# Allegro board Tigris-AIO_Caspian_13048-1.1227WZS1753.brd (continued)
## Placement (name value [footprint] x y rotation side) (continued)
C672  SCD1U16V2KX-3GP  [C402H22]  61.09 50.53 270 bottom
C673  SC10U16V6KX-2GP  [C1206H71]  129.32 49.77 270 bottom
C674  SCD1U16V2KX-3GP  [C402H22]  61.09 48.37 270 bottom
C675  SCD01U16V2KX-3GP  [C402H22]  57.1 48.78 0 bottom
C676  SCD1U16V2KX-3GP  [C402H22]  61.09 49.26 270 bottom
C677  SCD1U16V2KX-3GP  [C402H22]  61.09 46.97 270 bottom
C678  SCD1U16V2KX-3GP  [C402H22]  44.3 44.79 0 bottom
C679  SC3D3U10V5KX-2GP  [C805H38]  53.62 44.66 180 bottom
C680  SC10U25V5KX-GP  [C805H56]  45.75 43.9 180 bottom
C681  SCD01U16V2KX-3GP  [C402H22]  49.94 41.36 0 bottom
C682  SC10U25V5KX-GP  [C805H56]  161.67 36.05 90 bottom
C683  SCD1U16V2KX-3GP  [C402H22]  48.76 39.89 90 bottom
C684  SCD1U25V3KX-GP  [C603H36]  157.61 35.67 270 bottom
C685  SCD1U16V2KX-3GP  [C402H22]  61.85 38.08 180 bottom
C686  SCD1U16V2KX-3GP  [C402H22]  29.84 38.21 180 bottom
C687  SCD1U16V2KX-3GP  [C402H22]  27.94 38.08 180 bottom
C688  SCD1U16V2KX-3GP  [C402H22]  33.66 37.83 0 bottom
C689  SCD1U25V3KX-GP  [C603H36]  161.8 33.38 90 bottom
C690  SC10U25V5KX-GP  [C805H56]  157.42 33.16 270 bottom
C691  SCD1U16V2KX-3GP  [C402H22]  56.79 36.53 180 bottom
C692  SCD1U16V2KX-3GP  [C402H22]  18.16 36.56 0 bottom
C693  SCD1U16V2KX-3GP  [C402H22]  17.3 36.56 0 bottom
C694  SCD1U16V2KX-3GP  [C402H22]  12.85 36.56 180 bottom
C695  SCD1U16V2KX-3GP  [C402H22]  48.72 36.41 180 bottom
C696  SCD1U16V2KX-3GP  [C402H22]  59.27 35.91 90 bottom
C697  SC1U10V2KX-1GP  [C402H22]  26.67 35.8 270 bottom
C698  SCD1U16V2KX-3GP  [C402H22]  29.46 34.3 0 bottom
C699  SCD1U16V2KX-3GP  [C402H22]  33.66 34.4 180 bottom
C700  SCD1U16V2KX-3GP  [C402H22]  30.48 34.4 0 bottom
C701  SCD1U16V2KX-3GP  [C402H22]  28.07 34.43 0 bottom
C702  SC2D2U10V3KX-1GP  [C603H36]  36.83 34.02 90 bottom
C703  SCD1U16V2KX-3GP  [C402H22]  23.24 33.87 90 bottom
C704  SCD1U16V2KX-3GP  [C402H22]  131.5 32.7 0 bottom
C705  SCD1U16V2KX-3GP  [C402H22]  41.5 32.57 270 bottom
C706  SCD1U16V2KX-3GP  [C402H22]  44.53 32.65 90 bottom
C707  SC10U10V5KX-2GP  [C805H54]  132.97 32.34 0 bottom
C708  SC10P50V2JN-4GP  [C402H22]  10.01 25.46 0 top
C709  SCD1U16V2KX-3GP  [C402H22]  25.53 26.27 180 bottom
C710  SCD1U16V2KX-3GP  [C402H22]  25.96 30.84 90 bottom
C711  SC10P50V2JN-4GP  [C402H22]  10.01 27.37 180 top
C712  SCD1U16V2KX-3GP  [C402H22]  27.05 26.27 180 bottom
C713  SCD1U16V2KX-3GP  [C402H22]  64.14 28.43 0 bottom
C714  SCD1U10V2KX-4GP  [C402H20]  55.24 27.29 0 bottom
C715  SC10U10V5KX-2GP  [C805H54]  128.83 26.55 270 bottom
C716  SC1U10V2KX-1GP  [C402H22]  23.5 25.76 180 bottom
C717  SCD1U16V2KX-3GP  [C402H22]  22.1 25.64 180 bottom
C718  SC1U10V2KX-1GP  [C402H22]  19.05 25.59 0 bottom
C719  SCD1U16V2KX-3GP  [C402H22]  18.16 25.57 180 bottom
C720  SCD1U16V2KX-3GP  [C402H22]  129.13 24.01 270 bottom
C721  SCD1U10V2KX-4GP  [C402H20]  52.96 23.1 180 bottom
C722  SC100P50V2JN-3GP  [C402H22]  31.62 21.98 0 bottom
C723  SC100P50V2JN-3GP  [C402H22]  33.75 21.98 0 bottom
C724  SCD1U16V2KX-3GP  [C402H22]  63.75 21.19 180 bottom
C725  SCD1U16V2KX-3GP  [C402H22]  62.87 21.19 180 bottom
C726  SCD1U16V2KX-3GP  [C402H22]  34.85 15.96 180 bottom
C727  SC100P50V2JN-3GP  [C402H22]  33.43 15.43 270 bottom
C728  SC100P50V2JN-3GP  [C402H22]  33.93 14 180 bottom
C729  SC10U6D3V3MX-GP  [C603H38]  172.36 83.17 90 bottom
C732  SCD1U16V2KX-3GP  [C402H22]  25.6 141.74 180 top
C733  SCD1U25V3KX-GP  [C603H36]  28.7 147.68 180 top
C734  SCD47U25V3KX-1GP  [C603H36]  31.88 161.02 270 top
C735  SC1U25V3KX-1-GP  [C603H36]  26.04 154.54 90 top
C736  SCD22U10V2KX-1GP  [C402H22]  92.08 104.76 0 bottom
C737  SCD22U10V2KX-1GP  [C402H22]  81.15 106.38 0 bottom
C738  SCD22U10V2KX-1GP  [C402H22]  86.11 105.14 0 bottom
C739  SCD22U10V2KX-1GP  [C402H22]  84.2 106.41 0 bottom
C740  SCD22U10V2KX-1GP  [C402H22]  92.96 104.76 0 bottom
C741  SCD22U10V2KX-1GP  [C402H22]  90.3 103.62 0 bottom
C742  SCD22U10V2KX-1GP  [C402H22]  79.86 104.15 0 bottom
C743  SCD22U10V2KX-1GP  [C402H22]  88.27 107.3 0 bottom
C744  SCD22U10V2KX-1GP  [C402H22]  82.68 103.62 0 bottom
C745  SCD22U10V2KX-1GP  [C402H22]  87 105.14 0 bottom
C746  SCD22U10V2KX-1GP  [C402H22]  82.04 106.38 0 bottom
C747  SCD22U10V2KX-1GP  [C402H22]  85.09 106.41 0 bottom
C748  SCD22U10V2KX-1GP  [C402H22]  91.19 103.62 0 bottom
C749  SCD22U10V2KX-1GP  [C402H22]  78.97 104.15 0 bottom
C750  SCD22U10V2KX-1GP  [C402H22]  87.38 107.3 0 bottom
C751  SCD22U10V2KX-1GP  [C402H22]  83.57 103.62 0 bottom
C752  SC47P50V2JN-3GP  [C402H22]  94.49 94.73 0 top
C753  SCD1U10V2KX-5GP  [C402H22]  92.2 68.82 90 top
C755  SCD01U16V2KX-3GP  [C402H22]  112.52 75.68 0 top
C756  SC10P50V2JN-4DLGP  [C402H22]  94.49 96.76 0 top
C757  SC10P50V2JN-4DLGP  [C402H22]  94.49 98.79 180 top
C758  SC1U10V2KX-1GP  [C402H22]  92.71 87.49 0 bottom
C759  SC1U10V2KX-1GP  [C402H22]  91.69 87.49 0 bottom
C760  SC1U10V2KX-1GP  [C402H22]  76.2 101.2 270 bottom
C761  SC1U10V2KX-1GP  [C402H22]  71.88 102.22 90 bottom
C762  SC120P50V2JN-1GP  [C402H22]  80.26 75.93 180 bottom
C763  SCD1U16V2KX-3GP  [C402H22]  80.77 71.87 180 bottom
C764  SCD1U16V2KX-3GP  [C402H22]  74.3 71.87 0 top
C765  SC1U10V2KX-1GP  [C402H22]  45.85 92.82 270 top
C766  SC1U10V2KX-1GP  [C402H22]  45.85 94.73 270 top
C767  SC1U10V2KX-1GP  [C402H22]  73.66 80.25 180 bottom
C768  SC1U10V2KX-1GP  [C402H22]  76.25 92.08 270 bottom
C769  SC1U10V2KX-1GP  [C402H22]  76.28 92.97 270 bottom
C770  SC1U10V2KX-1GP  [C402H22]  76.28 93.86 270 bottom
C771  SC4D7U6D3V3KX-GP  [C603H36]  70.1 92.31 0 bottom
C772  SC22U6D3V5MX-2GP  [C805H58]  69.98 81.77 180 bottom
C773  SC1U10V2KX-1GP  [C402H22]  72.26 89.77 90 bottom
C774  SCD1U10V2KX-5GP  [C402H22]  71.88 88.25 90 bottom
C775  SC1U10V2KX-1GP  [C402H22]  71.12 86.47 90 bottom
C776  SC1U10V2KX-1GP  [C402H22]  62.61 90.28 0 bottom
C777  SC1U10V2KX-1GP  [C402H22]  76.07 84.82 270 bottom
C778  SC1U10V2KX-1GP  [C402H22]  75.06 81.64 270 bottom
C779  SC1U10V2KX-1GP  [C402H22]  84.81 90.46 180 bottom
C780  SC4D7U6D3V3KX-GP  [C603H36]  88.65 91.42 180 bottom
C781  SCD1U10V2KX-5GP  [C402H22]  85.7 90.46 180 bottom
C782  SC1U10V2KX-1GP  [C402H22]  85.72 87.92 180 bottom
C783  SC1U10V2KX-1GP  [C402H22]  84.84 87.92 180 bottom
C784  SC4D7U6D3V3KX-GP  [C603H36]  87.5 87.99 270 bottom
C785  SC1U10V2KX-1GP  [C402H22]  70.1 73.52 270 top
C786  SC1U10V2KX-1GP  [C402H22]  76.58 76.56 270 bottom
C787  SC4D7U6D3V3KX-GP  [C603H36]  69.72 71.48 270 top
C788  SC4D7U6D3V3KX-GP  [C603H36]  72.52 71.48 90 top
C789  SCD1U10V2KX-5GP  [C402H22]  70.1 72.63 270 top
C790  SCD1U10V2KX-5GP  [C402H22]  76.58 78.34 270 bottom
C791  SCD1U10V2KX-5GP  [C402H22]  76.58 77.45 270 bottom
C792  SCD1U10V2KX-5GP  [C402H22]  72.14 72.63 90 top
C793  SC1U10V2KX-1GP  [C402H22]  72.14 73.52 90 top
C794  SC1U10V2KX-1GP  [C402H22]  95.25 100.31 90 top
C795  SC1U10V2KX-1GP  [C402H22]  95.25 101.2 90 top
C796  SC1U10V2KX-1GP  [C402H22]  95.25 102.09 90 top
C797  SC4D7U6D3V3KX-GP  [C603H36]  95.38 103.23 90 top
C798  SC1U10V2KX-1GP  [C402H22]  80.75 93.13 0 bottom
C799  SC1U10V2KX-1GP  [C402H22]  79.86 93.13 0 bottom
C800  SC1U10V2KX-1GP  [C402H22]  78.97 93.13 0 bottom
C801  SC1U10V2KX-1GP  [C402H22]  77.85 95.49 270 bottom
C802  SC1U10V2KX-1GP  [C402H22]  78.49 94.6 270 bottom
C803  SC1U10V2KX-1GP  [C402H22]  78.49 91.32 90 bottom
C804  SC4D7U6D3V3KX-GP  [C603H36]  81.79 93.46 0 bottom
C805  SC1U10V2KX-1GP  [C402H22]  76.96 86.09 90 bottom
C806  SC1U10V2KX-1GP  [C402H22]  82.47 87.99 270 bottom
C807  SC1U10V2KX-1GP  [C402H22]  80.57 87.99 90 bottom
C808  SC1U10V2KX-1GP  [C402H22]  77.7 88.07 270 bottom
C809  SC1U10V2KX-1GP  [C402H22]  80.8 86.17 90 bottom
C810  SC4D7U6D3V3KX-GP  [C603H36]  76.33 90.28 0 bottom
C811  SC4D7U6D3V3KX-GP  [C603H36]  78.11 98.54 0 bottom
C812  SC4D7U6D3V3KX-GP  [C603H36]  79.3 98.54 0 bottom
C813  SC1U10V2KX-1GP  [C402H22]  81.76 84.34 270 bottom
C814  SC1U10V2KX-1GP  [C402H22]  84.05 86.52 270 bottom
C815  SC1U10V2KX-1GP  [C402H22]  78.21 84.52 270 bottom
C816  SC1U10V2KX-1GP  [C402H22]  76.3 87.54 180 bottom
C817  SC1U10V2KX-1GP  [C402H22]  81.66 82.66 180 bottom
C818  SC1U10V2KX-1GP  [C402H22]  79.76 89.62 270 bottom
C819  SC1U10V2KX-1GP  [C402H22]  83.31 89.65 270 bottom
C820  SCD1U10V2KX-5GP  [C402H22]  83.9 84.87 270 bottom
C821  SCD1U10V2KX-5GP  [C402H22]  80.77 96.76 180 bottom
C822  SC4D7U6D3V3KX-GP  [C603H36]  79.88 83.12 90 bottom
C823  SC1U10V2KX-1GP  [C402H22]  81.76 85.25 270 bottom
C824  SC1U10V2KX-1GP  [C402H22]  78.87 86.09 270 bottom
C825  SC1U10V2KX-1GP  [C402H22]  86.11 83.93 90 bottom
C826  SCD1U10V2KX-5GP  [C402H22]  86.11 84.82 90 bottom
C827  SC1U10V2KX-1GP  [C402H22]  88.01 83.93 270 bottom
C828  SC4D7U6D3V3KX-GP  [C603H36]  85.85 82.91 90 bottom
C829  SCD1U10V2KX-5GP  [C402H22]  88.11 84.82 270 bottom
C830  SC4D7U6D3V3KX-GP  [C603H36]  87.88 82.15 180 bottom
C831  SCD1U16V2KX-3GP  [C402H22]  165 186.04 270 bottom
C832  SCD1U16V2KX-3GP  [C402H22]  175.77 146.67 90 top
C833  SCD1U16V2KX-3GP  [C402H22]  156.59 188.32 180 bottom
C834  SCD1U16V2KX-3GP  [C402H22]  159.79 148.9 270 bottom
C835  SC1U10V2KX-1GP  [C402H22]  43.31 101.96 180 top
C836  SC10U16V6KX-2GP  [C1206H71]  17.65 195.79 270 top
C837  SC22U16V0KX-2-GP  [C1210H111]  42.29 106.54 0 top
C838  SC10U10V5KX-2GP  [C805H54]  187.71 131.94 0 top
C839  SC68P50V2JN-1GP  [C402H22]  81.03 79.87 0 bottom
C840  SC10U10V5KX-2GP  [C805H54]  174.88 223.71 270 bottom
C863  SC1U10V2KX-1GP  [C402H22]  19.2 30.75 0 top
C864  SC1U10V2KX-1GP  [C402H22]  94.64 240.46 0 bottom
C865  SC10P50V2JN-4DLGP  [C402H22]  150.42 59.05 0 top
C866  SC10P50V2JN-4DLGP  [C402H22]  149.53 64.67 180 top
C867  SC10P50V2JN-4DLGP  [C402H22]  145.54 62.43 180 bottom
C868  SC10P50V2JN-4DLGP  [C402H22]  141.58 68.49 270 bottom
C869  SCD1U16V2KX-3GP  [C402H22]  128.81 216.04 270 top
C870  SCD1U16V2KX-3GP  [C402H22]  144.2 74.91 270 bottom
CONVT1  JWT-CONN12D-S10-GP  [A2006WV0-2X6P-6T2-2D3]  6.86 119.05 90 top
CPU1  HASWE1NFU  [SKTBGA1150R740611UH367NF]  80.15 167.05 90 top
D1  RB551V30-GP  [SOD323AKH38]  70.87 231.12 270 top
D2  BAS40C-2-GP  [SOT-23-9H44]  70.61 227.95 0 top
D3  P6SMB27A-1-GP  [DO214AAAK-1121H97]  17.6 139.43 0 top
D5  BAV99GP-GP  [SOT23-2D4-312H48]  25.91 151.04 0 top
D6  IP4223CZ6-1-GP  [SOT-6H44]  187.1 116.32 90 top
D7  BAT54S-10-GP  [SOT-23-9H44]  113.41 79.1 90 top
D8  AZ5013-01HDR7G-GP  [SOD523AKH31]  22.48 41.77 180 top
D9  1SS355-4-GP  [SOD323AKH38]  117.07 37.58 90 top
D10  BAV99GP-GP  [SOT23-2D4-312H48]  13.06 35.57 90 top
D11  BAV99GP-GP  [SOT23-2D4-312H48]  13.13 31.56 90 top
D12  AZ5013-01HDR7G-GP  [SOD523AKH31]  19.51 27.95 90 top
D13  AZ5013-01HDR7G-GP  [SOD523AKH31]  17.27 26.91 180 top
D14  IP4223CZ6-1-GP  [SOT-6H44]  99.62 11.59 180 top
D15  IP4223CZ6-1-GP  [SOT-6H44]  125.4 10.83 0 top
D16  1SS355-4-GP  [SOD323AKH38]  11.18 182.61 90 bottom
D17  AZ2015-01H-GP  [SOD523AKH28]  175.26 76.56 270 bottom
D18  CH551H-30PT-GP  [SOD80CH36]  32.72 77.73 270 bottom
D19  1SS355-4-GP  [SOD323AKH38]  51.59 45.55 180 bottom
D20  BAV99GP-GP  [SOT23-2D4-312H48]  16.13 33.51 0 bottom
D21  BAV99GP-GP  [SOT23-2D4-312H48]  13.08 30.34 270 bottom
D22  1SS355-4-GP  [SOD323AKH38]  61.21 29.57 270 bottom
D23  1SS355-4-GP  [SOD323AKH38]  57.15 29.57 90 bottom
DB1  JOWLE-CON2-5-GP  [A2541WV0-1EX2PA-6T]  120.53 46.3 0 top
DIMM1  DDR3-204P-79-GP  [1932210-2]  168.3 156.05 90 top
DIMM2  DDR3-204P-80-GP  [1932208-2]  153.3 156.05 90 top
F1  FUSE-3A15V-GP  [FUSE-7452-UH50]  16.28 79.79 180 top
F2  POLYSW-1D5A8V-3-GP  [POLYSW-3217-UH40]  26.8 67.29 270 top
F3  POLYSW-1D5A8V-3-GP  [POLYSW-3217-UH40]  115.34 31.2 90 top
F4  POLYSW-1D5A8V-3-GP  [POLYSW-3217-UH40]  14.22 26.91 90 bottom
F5  POLYSW-2A8V-1-GP-U  [POLYSW-4633-UH24]  108.23 26.15 0 top
F6  POLYSW-1D5A8V-3-GP  [POLYSW-3217-UH40]  167.64 225.41 270 bottom
F7  POLYSW-1D5A8V-3-GP  [POLYSW-3217-UH40]  171.58 224.52 0 bottom
F8  POLYSW-2A8V-1-GP-U  [POLYSW-4633-UH24]  120.9 221.34 270 bottom
F9  FUSE-2A24V-3-GP  [FUSE-1005H17]  14.55 190.27 90 bottom
F10  FUSE-3A32V-25-GP  [FUSE-3216H26]  14.73 126.35 270 bottom
F11  POLYSW-2A8V-1-GP-U  [POLYSW-4633-UH24]  184.48 111.41 0 bottom
F12  FUSE-3A15V-GP  [FUSE-7452-UH50]  15.16 110.75 270 bottom
F13  POLYSW-1D5A8V-3-GP  [POLYSW-3217-UH40]  57.66 26.07 0 bottom
F14  POLYSW-1D5A8V-3-GP  [POLYSW-3217-UH40]  61.1 26.04 0 bottom
FANC1  TYCO-CON4-S3-GP  [HF08040-M1]  8.59 176.7 180 top
FANC2  CLX-CON4-S9-GP  [CI0104P1VKK-NH]  111.65 44.49 0 top
G1  COPPER-CLOSE-GP-U  [CON2C-U]  36.58 217.53 315 bottom
G2  COPPER-CLOSE-GP-U  [CON2C-U]  37.97 216.14 315 bottom
G3  COPPER-CLOSE-GP-U  [CON2C-U]  36.58 194.04 315 bottom
G4  COPPER-CLOSE-GP-U  [CON2C-U]  37.92 192.69 315 bottom
G5  COPPER-CLOSE-GP-U  [CON2C-U]  34.22 180.89 45 bottom
G6  COPPER-CLOSE-GP-U  [CON2C-U]  32.83 179.49 45 bottom
H1  HOLE  [HOLE236R157]  54.15 123.05 180 top
H2  -  [GEN315R138-8-F-A]  151.62 11.05 180 top
H3  HOLE  [HOLE236R157]  106.15 123.05 180 top
H4  HOLE  [HOLE236R157]  106.15 211.05 180 top
H5  HOLE  [HOLE236R157]  54.15 211.05 180 top
H7  GEN315R177-8-F-A-GP  [GEN315R177-8-F-A]  183.62 178.05 0 top
H8  -  [GEN315R138-8-F-A]  5.62 8.05 180 top
H11  GEN315R177-8-F-A-GP  [GEN315R177-8-F-A]  183.62 74.05 0 top
H12  -  [GEN315R138-8-F-A]  6.62 156.05 180 top
HDD1  MLX-CON7-10-GP  [67800-8035]  7.62 57.05 90 top
HDMI1  SKT-HDMI22-11-GP  [SKT-HDMI22-152071]  51.62 18.75 0 top
HS1  STF256R109H276-GP  [STF256R109H276]  160.02 93.55 0 top
HS2  STF256R109H398-GP  [STF256R109H398]  110.52 53.05 270 top
HS3  STF256R109H99-GP  [STF256R109H99]  84.37 237.55 90 top
INTRU1  FOX-CON3-S15-GP  [HF1103E-P1]  15.62 98.05 90 top
L1  COIL-D36UH-11-GP  [RT-D6-4D5-1010H375]  34.8 214.99 90 top
L2  HCB1608KF-800T30-GP  [L603H38]  124.33 213.6 90 top
L3  IND-D56UH-42-GP  [L112100-2135H158]  167.18 207.32 270 top
L4  HCB1608KF-800T30-GP  [L603H38]  130.96 203.13 90 top
L5  COIL-D36UH-11-GP  [RT-D6-4D5-1010H375]  34.8 192.01 90 top
L6  COIL-D36UH-11-GP  [RT-D6-4D5-1010H375]  34.73 177.84 180 top
L7  BLM15BD102SN1D-GP  [L402H22]  179.86 151.91 90 top
L8  BLM15BD102SN1D-GP  [L402H22]  14.73 151.62 0 top
L9  FILTER-4P-123-GP  [L125100-4P-1H36]  183.67 127.16 180 top
L10  FILTER-4P-123-GP  [L125100-4P-1H36]  183.67 125 180 top
L11  IND-1D5UH-53-GP  [L686647H119]  165.74 110.22 180 top
L12  FILTER-4P-123-GP  [L125100-4P-1H36]  184.51 105.5 180 top
L13  FILTER-4P-123-GP  [L125100-4P-1H36]  187.99 101.51 0 top
L14  IND-6D8UH-119-GP  [L109100-2230H158]  29.21 93.46 270 top
L15  IND-4D7UH-210-GP  [L3330-1230H95]  27.81 43.8 180 top
L16  MHC1608S221NBP-GP  [L603H38]  152.1 33.89 90 top
L17  FCM1005MF-750T03-GP  [L402H24]  35.41 22.62 270 top
L18  FCM1005MF-750T03-GP  [L402H24]  33.15 20.43 270 top
L19  FCM1005MF-750T03-GP  [L402H24]  37.39 20.68 270 top
L20  FCM1005KF-750T04-GP  [L402H24]  35.26 20.41 270 top
L21  FCM1005KF-750T04-GP  [L402H24]  31.11 19.49 90 top
L22  FCM1005KF-750T04-GP  [L402H24]  37.36 19.62 90 top
L23  MCB1005S121FBP-GP  [L402H24]  33.55 14.87 180 top
L24  MCB1005S121FBP-GP  [L402H24]  33.5 16.87 180 top
L25  MCB1005S121FBP-GP  [L402H24]  70.38 11.63 180 top
L26  MCB1005S121FBP-GP  [L402H24]  71.52 11.63 180 top
L27  HCB1608KF-800T30-GP  [L603H38]  118.49 217.66 0 bottom
L28  COIL-4D7UH-21-GP  [L3030-3009H40]  124.36 208.49 180 bottom
L29  BLM15BD102SN1D-GP  [L402H22]  183.9 153.53 270 bottom
L31  HCB1608KF-800T30-GP  [L603H38]  176.4 78.62 180 bottom
L33  MCB1005S121FBP-GP  [L402H24]  174.65 83.17 270 bottom
L40  MCB1005S121FBP-GP  [L402H24]  141.07 55.85 0 bottom
L41  HCB2012KF-601T20-GP  [L20125H42]  152.65 27.16 90 bottom
L42  HCB2012KF-601T20-GP  [L20125H42]  152.65 29.19 90 bottom
L43  HCB2012KF-601T20-GP  [L20125H42]  155.07 23.73 90 bottom
L44  HCB2012KF-601T20-GP  [L20125H42]  155.07 21.7 90 bottom
L45  MHC1608S800QBP-GP  [L603H38]  63.25 23.61 180 bottom
L46  -  [0R0805-PAD]  54.48 23.35 0 bottom
L47  MCB1005S121FBP-GP  [L402H24]  94.11 87.11 90 bottom
L48  MCB1005S121FBP-GP  [L402H24]  90.55 93.07 90 bottom
L49  MCB1005S121FBP-GP  [L402H24]  71.75 69.83 180 top
L50  MCB1005S121FBP-GP  [L402H24]  76.58 75.55 90 bottom
L51  MCB1005S121FBP-GP  [L402H24]  70.48 69.83 180 top
L52  MHC1608S221NBP-GP  [L603H38]  89.15 82.15 0 bottom
L53  MHC1608S221NBP-GP  [L603H38]  86.23 78.98 270 bottom
L54  MCB1005S121FBP-GP  [L402H24]  175.67 96 180 top
L56  FCM1005KF-301T03-GP  [L402H24]  145.21 18.93 270 top
LED1  LED-O-23-GP  [LED1608AKH30]  118.87 43.8 90 top
LED2  LED-O-23-GP  [LED1608AKH30]  125.27 30.82 0 bottom
LOUT1  AUDIO-JK419-GP  [JAC331-0140A8B-9H]  79.12 12.85 90 top
LPC1  FOX-CONN14A-S1-GP  [HL5507F]  128.3 39.4 0 top
LVDS1  ACES-CON30-21-GP  [50524-0300N-001]  138.62 227.15 180 top
M1  APL5930KAI-TRG-GP  [SOIC8-G3530H63]  133.09 51.07 270 top
MEJ1  JOWLE-CON2-5-GP  [A2541WV0-1EX2PA-6T]  171.96 97.52 0 top
MEM1  H5TQ1G63DFR-11C-1-GP  [BGA96D075130H48]  52.76 99.62 0 top
MEM2  H5TQ1G63DFR-11C-1-GP  [BGA96D075130H48]  52.76 79.56 180 top
MEM3  H5TQ1G63DFR-11C-1-GP  [BGA96D075130H48]  52.76 99.62 180 bottom
MEM4  H5TQ1G63DFR-11C-1-GP  [BGA96D075130H48]  52.76 79.56 0 bottom
MEMCD1  CARDBUS11P-SKT-GP  [PSDAT0-09GLBS1ZZ4H1]  193.52 154.05 90 top
NGFF1  SKT-MINI67P-3-GP-U1  [2199230-7]  112.62 237.55 90 top
NOREF  -  []  0 1 0 top
NOREF#2  -  [unnamed#2]  166.24 5.83 0 top
NOREF#3  -  [unnamed#2]  63.15 110.94 0 top
NOREF#4  -  [unnamed#2]  80.77 226.04 0 top
NOREF#5  -  [unnamed#2]  4.9 237.27 0 top
NOREF#6  -  []  0 1 0 top
NOREF#7  -  [unnamed#2]  203.44 243.18 0 top
NOREF#8  -  []  0 1 0 top
NOREF#9  -  [unnamed#2]  72.01 109.71 0 top
NOREF#10  -  [unnamed#2]  208.03 247.76 0 top
NOREF#11  -  []  0 1 0 top
NOREF#12  -  [unnamed#2]  104.44 53.98 0 top
NOREF#13  -  [unnamed#2]  182.52 219.85 0 top
NOREF#14  -  []  0 1 0 top
NOREF#15  -  [unnamed#2]  75.08 242.5 0 top
NOREF#16  -  [unnamed#2]  200.22 11.79 0 top
NOREF#17  -  []  137.59 173.34 0 top
NOREF#18  -  [unnamed#2]  106.93 69.58 0 top
NOREF#19  -  [unnamed#2]  97.15 110.94 0 top
NOREF#20  -  [unnamed#2]  166.5 93.96 0 top
NOREF#21  -  [unnamed#2]  62.23 122.03 0 top
NOREF#22  -  [unnamed#2]  80.15 59.34 0 top
NOREF#23  -  []  112.65 197.14 0 top
NOREF#24  -  []  122.43 146.54 270 top
NOREF#25  -  []  0 1 0 top
NOREF#26  -  [unnamed#2]  9.55 15.12 0 top
NOREF#27  -  [unnamed#2]  206.16 8.62 0 top
NOREF#28  -  [unnamed#2]  182.52 219.85 180 bottom
NOREF#29  -  [unnamed#2]  203.44 243.18 180 bottom
NOREF#30  -  [unnamed#2]  166.24 5.8 180 bottom
NOREF#31  -  [unnamed#2]  9.55 15.12 180 bottom
NOREF#32  -  [unnamed#2]  5.49 227.34 180 bottom
NOREF#33  -  [unnamed#2]  200.22 11.79 180 bottom
ODD1  MLX-CON7-10-GP  [67800-8035]  7.62 78.05 90 top
PC1  SC1U10V2KX-1GP  [C402H22]  90.99 230.79 90 top
PC2  SC22P50V2JN-4GP  [C402H22]  161.67 223.38 0 top
PC3  SC22P50V2JN-4GP  [C402H22]  181.99 188.58 180 top
PC4  SC22P50V2JN-4GP  [C402H22]  38.1 148.19 90 top
PC5  SCD22U25V3KX-GP  [C603H40]  35.56 148.45 0 top
PC6  SC150P50V2JN-3GP  [C402H22]  38.1 147.3 270 top
PC7  SC1KP50V2KX-1GP  [C402H22]  40.13 146.29 270 top
PC8  SC33P50V2JN-3GP  [C402H22]  38.73 145.78 0 top
PC9  SCD01U50V2KX-1GP  [C402H22]  42.39 145.73 180 top
PC10  SCD22U25V3KX-GP  [C603H40]  34.75 143.98 90 top
PC11  SC390P50V2KX-GP  [C402H22]  33.73 142.78 90 top
PC12  SCD1U25V3KX-GP  [C603H36]  47.35 142.68 270 top
PC13  SC330P50V2KX-3GP  [C402H22]  35.26 142.27 0 top
PC14  SCD01U50V2KX-1GP  [C402H22]  33.66 137.35 90 top
PC15  SCD033U25V2KX-GP  [C402H22]  32.72 135.19 0 top
PC16  SCD22U25V3KX-GP  [C603H40]  34.8 134.83 0 top
PC17  SC1U16V3KX-5GP  [C603H36]  41.91 133.94 0 top
PC18  SC1U16V3KX-5GP  [C603H36]  43.1 133.94 0 top
PC19  SCD22U25V3KX-GP  [C603H40]  37.8 133.66 270 top
PC20  SCD1U25V3KX-GP  [C603H36]  34.77 132.11 180 top
PC21  SCD01U25V2KX-3GP  [C402H22]  118.03 113.76 0 top
PC22  SC10U16V6KX-2GP  [C1206H71]  132.84 113.14 90 top
PC23  SCD1U10V2KX-5GP  [C402H22]  133.22 111.49 270 top
PC24  SC10U25V6KX-4DL-GP  [C1206H71]  21.84 105.9 0 top
PC25  SCD1U10V2KX-5GP  [C402H22]  121.84 105.72 270 top
PC26  SC1U16V3KX-5GP  [C603H36]  128.7 105.62 90 top
PC27  SCD047U16V2KX-1-GP  [C402H22]  120.74 103.77 0 top
PC28  SCD1U10V2KX-5GP  [C402H22]  115.64 103.45 180 top
PC29  SC4D7U16V5KX-1-GP  [C805H56]  117.09 103.35 0 top
PC30  SC4700P50V2KX-1GP  [C402H22]  129.03 103.03 0 top
PC31  SC1KP50V2KX-1GP  [C402H22]  127.64 102.57 90 top
PC32  SCD047U16V2KX-1-GP  [C402H22]  127.64 101.69 90 top
PC33  SC22P50V2JN-4GP  [C402H22]  156.77 99.7 180 top
PC34  SCD1U10V2KX-5GP  [C402H22]  149.78 98.46 0 top
PC35  SCD1U16V2KX-3GP  [C402H22]  111.89 67.42 90 top
PC36  SCD1U10V2KX-5GP  [C402H22]  49.33 66.7 270 top
PC37  SC150P50V2JN-3GP  [C402H22]  101.01 66.03 270 top
PC38  SC1U16V3KX-5GP  [C603H36]  111.58 64.14 270 top
PC39  SC10U16V6KX-2GP  [C1206H71]  98.55 61.32 0 top
PC40  SC10U16V6KX-2GP  [C1206H71]  100.84 61.32 0 top
PC41  SC10U16V6KX-2GP  [C1206H71]  105.16 59.29 0 top
PC42  SC10U25V6KX-4DL-GP  [C1206H71]  71.7 47.35 180 top
PC43  SCD01U50V2KX-1GP  [C402H22]  73.25 47.28 180 top
PC44  SCD1U25V3KX-GP  [C603H36]  95.5 43.42 180 top
PC45  SC1U16V3KX-5GP  [C603H36]  90.63 41.44 90 top
PC46  SC22P50V2JN-4GP  [C402H22]  100.58 41.39 90 top
PC47  SC4D7U16V5KX-1-GP  [C805H56]  90.25 37.63 270 top
PC48  SC4D7U16V5KX-1-GP  [C805H56]  90.25 35.47 270 top
PC49  SCD1U25V3KX-GP  [C603H36]  94.23 33.64 180 top
PC50  SC1U6D3V3KX-2GP  [C603H36]  98.35 33.44 0 top
PC51  SC22P50V2JN-4GP  [C402H22]  100.08 32.24 270 top
PC52  SC10U25V6KX-4DL-GP  [C1206H71]  68.07 29.75 0 top
PC53  SCD01U50V2KX-1GP  [C402H22]  69.85 28.99 0 top
PC54  SC1U16V3KX-5GP  [C603H36]  101.07 25.66 90 top
PC55  SC1500P50V3KX-GP  [C603]  82.8 22.21 90 top
PC56  SC330P50V2KX-3GP  [C402H22]  38.99 141.08 270 bottom
PC57  SC1KP50V2KX-1GP  [C402H22]  38.99 140.19 270 bottom
PC58  SC1U16V3KX-5GP  [C603H36]  39.12 139.18 270 bottom
PC59  SCD1U16V3KX-3GP  [C603H36]  33.32 138.62 180 bottom
PC60  SCD22U25V3KX-GP  [C603H40]  39.12 137.98 90 bottom
PC61  SC10U25V6KX-4DL-GP  [C1206H71]  23.75 122.92 270 bottom
PC62  SCD1U25V3KX-GP  [C603H36]  23.62 120.89 90 bottom
PC63  SC10U25V6KX-4DL-GP  [C1206H71]  23.75 119.11 270 bottom
PC64  SC10U25V6KX-4DL-GP  [C1206H71]  21.84 105.9 180 bottom
PC65  SC1500P50V3KX-GP  [C603]  27.81 103.23 180 bottom
PC66  SC1500P50V3KX-GP  [C603]  78.11 52.05 90 bottom
PC67  SC1U6D3V3KX-2GP  [C603H36]  98.86 45.4 270 bottom
PC68  SC10U25V6KX-4DL-GP  [C1206H71]  78.97 39.43 270 bottom
PC69  SC1U25V3KX-GP  [C603H36]  88.9 38.54 180 bottom
PC70  SCD1U50V3KX-GP  [C603H36]  90.2 38.52 180 bottom
PC71  SC10U25V6KX-4DL-GP  [C1206H71]  78.97 37.02 270 bottom
PC72  SC1U10V2KX-1GP  [C402H22]  21.08 25.64 180 bottom
PC73  SCD01U50V2KX-1GP  [C402H22]  83.19 83.17 90 bottom
PG1  GAP-CLOSE-PWR-3-GP  [GAP-CLOSE-PWR-3]  92.58 35.29 270 top
PG2  GAP-CLOSE-PWR-3-GP  [GAP-CLOSE-PWR-3]  100.2 27.16 90 top
PG3  GAP-CLOSE  [CON2C]  33.91 115.55 225 bottom
PG4  GAP-CLOSE  [CON2C]  33.1 114.18 225 bottom
PG5  GAP-CLOSE-PWR-3-GP  [GAP-CLOSE-PWR-3]  97 45.07 90 bottom
PG6  GAP-CLOSE-PWR-3-GP  [GAP-CLOSE-PWR-3]  91.54 37.47 180 bottom
PL1  COIL-D36UH-11-GP  [RT-D6-4D5-1010H375]  32.82 115.53 180 top
PL2  IND-3D3UH-135-GP  [L115100-2230H158]  88.01 48.37 270 top
PL3  IND-3D3UH-135-GP  [L115100-2230H158]  84.53 28.81 90 top
PL4  MHC2012S221QBP-GP  [L805H44]  72.36 42.22 270 bottom
PL5  MHC2012S221QBP-GP  [L805H44]  72.36 40.29 270 bottom
PL6  MHC2012S221QBP-GP  [L805H44]  72.36 38.36 270 bottom
PL7  MHC2012S221QBP-GP  [L805H44]  72.36 36.43 270 bottom
PR1  0R2J-2-GP  [R402H16]  38.1 149.21 90 top
PR2  -  [0R0402-PAD]  42.04 148.32 270 top
PR3  1KR2J-1-GP  [R402H16]  44.55 147.76 180 top
PR4  1KR2J-1-GP  [R402H16]  45.69 147.76 0 top
PR5  4K02R2F-GP  [R402H16]  42.04 147.3 270 top
PR6  1K91R2F-1-GP  [R402H16]  46.96 146.11 90 top
PR7  1KR2J-1-GP  [R402H16]  49.76 146.11 90 top
PR8  47KR2F-GP  [R402H16]  37.72 145.78 0 top
PR9  47KR2F-GP  [R402H16]  43.41 145.73 180 top
PR10  -  [0R0402-PAD]  44.55 145.73 180 top
PR11  0R0402-PAD-2-GP  [0R0402-PAD-1]  34.47 145.53 180 top
PR12  0R0402-PAD-2-GP  [0R0402-PAD-1]  35.51 145.53 0 top
PR13  8K06R2F-GP  [R402H16]  40.13 145.27 270 top
PR14  -  [0R0402-PAD]  46.96 144.97 90 top
PR15  1KR2J-1-GP  [R402H16]  49.76 144.97 270 top
PR16  910R2F-1-GP  [R402H16]  32.38 144 270 top
PR17  -  [0R0402-PAD]  46.96 143.82 270 top
PR18  -  [0R0402-PAD]  49.76 143.82 270 top
PR19  10KR2F-2-GP  [R402H16]  49.76 142.68 270 top
PR20  562R2F-GP  [R402H16]  32.08 142.27 180 top
PR21  2KR2F-3-GP  [R402H16]  33.73 141.77 90 top
PR22  100R2F-L1-GP-U  [R402H14]  36.2 141.51 0 top
PR23  -  [0R0402-PAD]  47.09 141.41 270 top
PR24  1KR2J-1-GP  [R402H16]  49.76 141.41 90 top
PR25  -  [0R0402-PAD]  47.09 140.4 270 top
PR26  1KR2J-1-GP  [R402H16]  49.76 140.4 90 top
PR27  100R2F-L1-GP-U  [R402H14]  33.66 140.7 90 top
PR28  -  [0R0402-PAD]  82.68 81.77 180 bottom
PR29  -  [0R0402-PAD]  83.82 81.77 180 bottom
PR30  -  [0R0402-PAD]  47.09 139.38 270 top
PR31  1KR2J-1-GP  [R402H16]  49.76 139.38 90 top
PR32  -  [0R0402-PAD]  47.09 138.36 270 top
PR33  1KR2J-1-GP  [R402H16]  49.76 138.36 90 top
PR34  82D5R2F-1-GP  [R402H16]  35.69 137.35 270 top
PR35  -  [0R0402-PAD]  47.09 137.35 270 top
PR36  1KR2J-1-GP  [R402H16]  49.76 137.35 90 top
PR37  -  [0R0402-PAD]  47.09 136.33 270 top
PR38  1KR2J-1-GP  [R402H16]  49.76 136.33 90 top
PR39  -  [0R0402-PAD]  47.09 135.32 270 top
PR40  1KR2J-1-GP  [R402H16]  49.76 135.32 90 top
PR41  11KR2F-L-GP  [R402H16]  33.68 135.21 0 top
PR42  2K61R2F-1-GP  [R402H16]  35.92 135.21 0 top
PR43  2D2R2F-GP  [R402H16]  36.96 135.21 0 top
PR44  -  [0R0402-PAD]  44.22 135.04 180 top
PR45  3K65R3F-GP  [R603H22]  31.37 132.06 0 top
PR46  10KR2F-2-GP  [R402H16]  32.61 131.71 0 top
PR47  1R2F-GP  [R402H16]  33.66 131.71 0 top
PR48  -  [0R0805-PAD]  21.46 131.17 180 top
PR49  -  [0R0805-PAD]  22.86 131.17 180 top
PR50  -  [0R0805-PAD]  24.26 131.17 180 top
PR51  NTC-10K-27-GP  [NTC-402H24]  36.35 122.01 270 top
PR52  0R0805-PAD-2-GP  [0R0805-PAD-1]  48.77 118.6 90 top
PR53  0R0805-PAD-2-GP  [0R0805-PAD-1]  48.77 117.2 90 top
PR54  100R5J-4-GP  [R805H24]  120.83 117.03 180 top
PR55  0R0805-PAD-2-GP  [0R0805-PAD-1]  48.77 115.81 90 top
PR56  0R0805-PAD-2-GP  [0R0805-PAD-1]  48.77 114.41 90 top
PR57  0R0805-PAD-2-GP  [0R0805-PAD-1]  48.77 113.01 90 top
PR58  0R0805-PAD-2-GP  [0R0805-PAD-1]  48.77 111.62 90 top
PR59  0R0805-PAD-2-GP  [0R0805-PAD-1]  48.77 110.22 90 top
PR60  NTC-470K-9-GP  [NTC-402H24]  24.18 108.65 90 top
PR61  10KR2J-3-GP  [R402H16]  123.8 105.8 270 top
PR62  10R2F-L-GP  [R402H14]  119.72 103.77 180 top
PR63  0R0402-PAD-2-GP  [0R0402-PAD-1]  118.62 103.73 180 top
PR64  10KR2F-2-GP  [R402H16]  127.64 103.54 90 top
PR65  -  [0R0805-PAD]  109.87 103.36 0 top
PR66  -  [0R0805-PAD]  111.9 103.36 0 top
PR67  -  [0R0805-PAD]  113.93 103.36 0 top
PR68  24KR2F-GP  [R402H16]  130 103.03 180 top
PR69  4K53R2F-1-GP  [R402H16]  120.23 102.27 90 top
PR70  100KR2F-L1-GP  [R402H16]  150.24 99.93 270 top
PR71  10KR2J-3-GP  [R402H16]  167.91 84.37 0 top
PR72  0R3J-0-U-GP  [R603H22]  26.39 72.93 90 top
PR73  0R3J-0-U-GP  [R603H22]  26.37 71.46 90 top
PR74  12KR2F-L-GP  [R402H16]  101.98 68.18 270 top
PR75  0R2J-2-GP  [R402H16]  49.33 67.72 90 top
PR76  -  [0R0805-PAD]  99.06 67.29 180 top
PR77  15K4R2F-GP  [R402H16]  101.01 67.04 270 top
PR78  0R2J-2-GP  [R402H16]  111.85 66.41 270 top
PR79  -  [0R0402-PAD]  139.19 51.83 270 top
PR80  2D2R5F-2-GP  [R805H24]  97.16 43.8 180 top
PR81  100KR2J-1-GP  [R402H16]  98.81 42.99 0 top
PR82  6K65R2F-GP  [R402H16]  100.58 40.37 90 top
PR83  21K5R2F-GP  [R402H16]  90.98 40.19 270 top
PR84  10KR2F-2-GP  [R402H16]  100.58 39.35 90 top
PR85  10KR2F-2-GP  [R402H16]  91.01 39.15 270 top
PR86  68KR2F-GP  [R402H16]  100.58 37.32 90 top
PR87  150KR2F-L-GP  [R402H16]  100.58 36.31 270 top
PR88  10KR2F-2-GP  [R402H16]  100.36 35.29 90 top
PR89  15KR2F-GP  [R402H16]  99.92 34.25 270 top
PR90  2D2R5F-2-GP  [R805H24]  95.89 33.26 180 top
PR91  2D2R5F-2-GP  [R805H24]  79.63 22.21 90 top
PR92  0R3J-0-U-GP  [R603H22]  18.79 185.56 0 bottom
PR93  0R3J-0-U-GP  [R603H22]  17.55 185.56 0 bottom
PR94  1KR2J-1-GP  [R402H16]  49.76 141.41 90 bottom
PR95  1R2F-GP  [R402H16]  33.88 140.52 270 bottom
PR96  1KR2J-1-GP  [R402H16]  49.76 140.4 90 bottom
PR97  1KR2J-1-GP  [R402H16]  49.76 139.38 90 bottom
PR98  0R0603-PAD-2-GP-U  [0R0603-PAD-1-U]  34.59 138.62 0 bottom
PR99  9K31R2F-GP  [R402H16]  32.18 138.62 180 bottom
PR100  1KR2J-1-GP  [R402H16]  49.76 138.36 90 bottom
PR101  -  [0R0402-PAD]  36.83 137.52 270 bottom
PR102  1KR2J-1-GP  [R402H16]  49.76 137.35 90 bottom
PR103  1KR2J-1-GP  [R402H16]  49.76 136.33 90 bottom
PR104  1KR2J-1-GP  [R402H16]  49.76 135.32 90 bottom
PR105  1R5J-2-GP  [R805H24]  29.34 120.51 270 bottom
PR106  0R0805-PAD-2-GP  [0R0805-PAD-1]  49.4 118.47 270 bottom
PR107  0R0805-PAD-2-GP  [0R0805-PAD-1]  49.4 117.08 270 bottom
PR108  0R3J-0-U-GP  [R603H22]  15.18 117.25 180 bottom
PR109  0R3J-0-U-GP  [R603H22]  13.93 117.25 180 bottom
PR110  0R0805-PAD-2-GP  [0R0805-PAD-1]  49.4 115.68 270 bottom
PR111  0R0805-PAD-2-GP  [0R0805-PAD-1]  49.4 114.28 270 bottom
PR112  0R0805-PAD-2-GP  [0R0805-PAD-1]  49.4 112.89 270 bottom
PR113  0R0805-PAD-2-GP  [0R0805-PAD-1]  49.4 111.49 270 bottom
PR114  2D2R5J-1-GP  [R805H24]  27.81 106.54 180 bottom
PR115  2D2R5F-2-GP  [R805H24]  81.28 51.93 90 bottom
PR116  0R0805-PAD-2-GP-U  [0R0805-PAD-1-U]  79.98 44.92 180 bottom
PR117  100KR2F-L1-GP  [R402H16]  91.47 38.9 180 bottom
PR118  0R0805-PAD-2-GP-U  [0R0805-PAD-1-U]  80.64 32.75 90 bottom
PSWD1  JOWLE-CON2-5-GP  [A2541WV0-1EX2PA-6T]  151.35 111.87 270 top
PT1  E820U2D5VM-7-GP  [ECAP-100D6D3H355]  42.8 128.66 0 top
PT2  SE47U25VM-14-GP  [SE361416H237]  23.24 125.59 90 top
PT3  E820U2D5VM-7-GP  [ECAP-100D6D3H355]  42.8 120.79 0 top
PT4  E820U2D5VM-7-GP  [ECAP-100D6D3H355]  42.77 112.96 0 top
PTC1  SE220U6D3VM-8GP  [SE331721H237]  98.55 51.04 180 top
PTC2  SE220U6D3VM-8GP  [SE331721H237]  95.25 26.78 180 top
PU1  SIR172ADP-T1-GE3-GP  [PPAK-5PH45]  21.72 118.6 90 top
PU2  SIR172ADP-T1-GE3-GP  [PPAK-5PH45]  21.72 112.25 90 top
PU3  SIRA12DP-T1-GE3-GP  [PPAK-5PH45]  28.32 105.9 0 top
PU4  SIRA12DP-T1-GE3-GP  [PPAK-5PH45]  34.8 105.9 0 top
PU5  APL5930KAI-TRG-1-GP  [SOIC8-G3530H63]  105.91 64.63 270 top
PU6  RT8243BZQW-GP  [QFN20-G1D75H32]  95.94 38.19 270 top
PWRCN1  JWT-CONN10D-S8-GP  [A2006WV0-2X5P-6T2-2D3]  6.62 37.05 90 top
Q1  2N7002K-2-GP  [SOT23DGS2D4H44]  94.15 240.62 180 top
Q2  2N7002K-2-GP  [SOT23DGS2D4H44]  94.15 236.68 180 top
Q3  2N7002A-7-GP  [SOT23DGS2D4H48]  94.26 232.97 90 top
Q4  AO3413L-GP  [SOT23DGS2D8H50]  94.31 229.4 270 top
Q5  SIRA12DP-T1-GE3-GP  [PPAK-5PH45]  28.83 224.14 180 top
Q6  SIRA12DP-T1-GE3-GP  [PPAK-5PH45]  37.21 224.14 180 top
Q7  MMBT3904-4-GP  [SOT23CBE2D4H44]  115.82 219.69 90 top
Q8  SIR172ADP-T1-GE3-GP  [PPAK-5PH45]  23.62 217.79 90 top
Q9  MMBT3904DW-1-GP  [SOT-363H44]  64.9 217.28 0 top
Q10  SIR172ADP-T1-GE3-GP  [PPAK-5PH45]  170.71 217.97 0 top
Q11  MMBT3904DW-1-GP  [SOT-363H44]  65.66 213.34 270 top
Q12  SIR172ADP-T1-GE3-GP  [PPAK-5PH45]  23.62 211.44 90 top
Q13  SIRA12DP-T1-GE3-GP  [PPAK-5PH45]  176.94 209.71 90 top
Q14  MMBT3904-4-GP  [SOT23CBE2D4H44]  136.53 208.9 90 top
Q15  MMBT3904-4-GP  [SOT23CBE2D4H44]  135.25 204.2 0 top
Q16  SIRA12DP-T1-GE3-GP  [PPAK-5PH45]  29.21 201.15 180 top
Q17  SIRA12DP-T1-GE3-GP  [PPAK-5PH45]  37.59 201.15 180 top
Q18  SIRA12DP-T1-GE3-GP  [PPAK-5PH45]  176.91 201.43 90 top
Q19  MMBT3904-4-GP  [SOT23CBE2D4H44]  130.99 199.02 0 top
Q20  MMBT3904-4-GP  [SOT23CBE2D4H44]  135.13 198.99 0 top
Q21  SIR172ADP-T1-GE3-GP  [PPAK-5PH45]  23.5 194.42 90 top
Q22  MMBT3904-4-GP  [SOT23CBE2D4H44]  176.66 191.37 90 top
Q23  SIR172ADP-T1-GE3-GP  [PPAK-5PH45]  23.5 188.1 90 top
Q24  SIR172ADP-T1-GE3-GP  [PPAK-5PH45]  23.5 181.34 90 top
Q25  SIR172ADP-T1-GE3-GP  [PPAK-5PH45]  23.52 175.04 90 top
Q26  MMBT3904-4-GP  [SOT23CBE2D4H44]  45.87 169.38 0 top
Q27  SIRA12DP-T1-GE3-GP  [PPAK-5PH45]  29.3 168.75 0 top
Q28  SIRA12DP-T1-GE3-GP  [PPAK-5PH45]  37.68 168.75 0 top
Q35  MMBT3904-4-GP  [SOT23CBE2D4H44]  142.37 140.12 0 top
Q36  MMBT3904-4-GP  [SOT23CBE2D4H44]  22.1 150.86 0 top
Q37  2N7002A-7-GP  [SOT23DGS2D4H48]  18.31 150.66 180 top
Q38  MMBT3904-4-GP  [SOT23CBE2D4H44]  14.99 114.54 90 top
Q39  SI4712DY-T1-GE3-GP  [SOIC8H69]  173.99 112.51 90 top
Q40  QM3004D-GP  [SMD-TO-252-DGS6698H99]  120.24 111.44 270 top
Q41  SI4128DY-T1-GE3-GP  [SOIC8H69]  173.99 104.84 270 top
Q42  AZ5125-02S-R7G-GP  [SOT23-2D4-312H46]  183.64 87.11 270 bottom
Q44  MMBT3904DW-1-GP  [SOT-363H44]  168.56 81.56 0 top
Q45  MMBT3904DW-1-GP  [SOT-363H44]  171.96 80.63 90 top
Q46  2N7002A-7-GP  [SOT23DGS2D4H48]  200.15 76.95 0 top
Q48  MMBT3904-4-GP  [SOT23CBE2D4H44]  109.61 75.13 90 top
Q49  2N7002A-7-GP  [SOT23DGS2D4H48]  196.04 73.87 270 top
Q51  DMP2130L-7-GP  [SOT23DGS2D4H48]  85.06 69.34 0 top
Q52  MMBT3906-4-GP  [SOT23CBE2D4H44]  156.08 68.34 270 top
Q53  MMBT3904-4-GP  [SOT23CBE2D4H44]  78.05 66.19 270 top
Q54  2N7002KDW-1-GP  [SOT-363H44]  85.98 65.39 0 top
Q55  2N7002A-7-GP  [SOT23DGS2D4H48]  49.07 64.29 180 top
Q56  2N7002A-7-GP  [SOT23DGS2D4H48]  53.9 63.91 0 top
Q57  AO4468L-GP  [SOIC8H69]  67.31 62.47 270 top
Q58  AO3401AL-GP  [SOT23DGS2D8H50]  35.56 60.69 0 top
Q59  MMBT3904-4-GP  [SOT23CBE2D4H44]  43.66 58.84 180 top
Q60  2N7002A-7-GP  [SOT23DGS2D4H48]  49.15 58.78 0 top
Q61  2N7002A-7-GP  [SOT23DGS2D4H48]  145.92 46.59 270 top
Q62  MMBT3904DW-GP  [SOT-363H44]  145.8 52.31 0 top
Q63  2N7002A-7-GP  [SOT23DGS2D4H48]  149.22 52.31 0 top
Q64  SI4712DY-T1-GE3-GP  [SOIC8H69]  77.42 50.53 270 top
Q65  SI4128DY-T1-GE3-GP  [SOIC8H69]  77.42 44.87 90 top
Q66  MMBT3904DW-GP  [SOT-363H44]  38.35 44.69 180 top
Q67  MMBT3904-4-GP  [SOT23CBE2D4H44]  13.06 43.06 90 top
Q68  MMBT3904-4-GP  [SOT23CBE2D4H44]  16.76 43.04 180 top
Q69  2N7002A-7-GP  [SOT23DGS2D4H48]  103.89 42.02 90 top
Q70  MMBT3904-4-GP  [SOT23CBE2D4H44]  13.08 39.48 90 top
Q71  2N7002A-7-GP  [SOT23DGS2D4H48]  107.95 38.34 90 top
Q72  2N7002A-7-GP  [SOT23DGS2D4H48]  111.84 38.34 90 top
Q73  2N7002A-7-GP  [SOT23DGS2D4H48]  103.89 38.34 90 top
Q74  MMBT3904DW-1-GP  [SOT-363H44]  41.78 33.77 180 top
Q75  AO4468L-GP  [SOIC8H69]  106.88 32.22 90 top
Q76  2N7002A-7-GP  [SOT23DGS2D4H48]  136.5 32.11 90 top
Q77  SI4128DY-T1-GE3-GP  [SOIC8H69]  74.09 31.51 90 top
Q78  AO4468L-GP  [SOIC8H69]  126.11 31.48 90 top
Q79  2N7002A-7-GP  [SOT23DGS2D4H48]  163.19 22.49 270 top
Q80  AO3413L-GP  [SOT23DGS2D8H50]  31.7 26.68 0 top
Q81  SI4712DY-T1-GE3-GP  [SOIC8H69]  74.09 25.87 270 top
Q82  AO4468L-GP  [SOIC8H69]  126.11 25.71 90 top
Q83  2N7002A-7-GP  [SOT23DGS2D4H48]  163.19 18.91 90 top
Q84  2N7002A-7-GP  [SOT23DGS2D4H48]  65.97 21.71 180 top
Q85  AZ5125-02S-R7G-GP  [SOT23-2D4-312H46]  71.08 14.94 0 top
Q86  MMBT3904DW-1-GP  [SOT-363H44]  6.93 245.35 270 bottom
Q87  MMBT3904DW-1-GP  [SOT-363H44]  5.97 242.27 90 bottom
Q88  2N7002K-2-GP  [SOT23DGS2D4H44]  102.74 241.41 90 bottom
Q89  MMBT3904-4-GP  [SOT23CBE2D4H44]  6.27 235.95 270 bottom
Q90  2N7002A-7-GP  [SOT23DGS2D4H48]  114.17 223.88 90 bottom
Q91  2N7002A-7-GP  [SOT23DGS2D4H48]  115.82 219.69 270 bottom
Q92  2N7002A-7-GP  [SOT23DGS2D4H48]  120.14 211.18 90 bottom
Q93  2N7002A-7-GP  [SOT23DGS2D4H48]  116.33 211.18 90 bottom
Q94  2N7002A-7-GP  [SOT23DGS2D4H48]  120.4 205.47 0 bottom
Q95  2N7002A-7-GP  [SOT23DGS2D4H48]  116.71 205.47 0 bottom
Q96  2N7002A-7-GP  [SOT23DGS2D4H48]  180.85 96.25 180 bottom
Q97  AZ5125-02S-R7G-GP  [SOT23-2D4-312H46]  185.95 91.57 270 bottom
Q98  2N7002A-7-GP  [SOT23DGS2D4H48]  33.91 67.8 270 bottom
Q99  2N7002A-7-GP  [SOT23DGS2D4H48]  138.68 50.82 90 bottom
Q100  2N7002A-7-GP  [SOT23DGS2D4H48]  134.74 50.82 90 bottom
Q101  MMBT3904DW-1-GP  [SOT-363H44]  134.62 47.26 90 bottom
Q102  MMBT3904-4-GP  [SOT23CBE2D4H44]  57.53 44.31 180 bottom
Q103  2N7002A-7-GP  [SOT23DGS2D4H48]  16.76 43.09 90 bottom
Q104  MMBT3904DW-1-GP  [SOT-363H44]  61.87 41.67 90 bottom
Q105  MMBT3904-4-GP  [SOT23CBE2D4H44]  53.64 41 90 bottom
Q106  MMBT3904DW-1-GP  [SOT-363H44]  45.09 40.24 90 bottom
Q107  2N7002A-7-GP  [SOT23DGS2D4H48]  16.79 39.4 270 bottom
Q108  MMBT3904-4-GP  [SOT23CBE2D4H44]  109.91 38.51 90 bottom
Q109  MMBT3904DW-1-GP  [SOT-363H44]  45.09 37.07 270 bottom
Q110  MMBT3904DW-1-GP  [SOT-363H44]  52.32 35.92 270 bottom
Q111  MMBT3904DW-1-GP  [SOT-363H44]  48.51 33.77 270 bottom
Q112  AO3401AL-GP  [SOT23DGS2D8H50]  122.6 32.78 180 bottom
Q113  2N7002A-7-GP  [SOT23DGS2D4H48]  54.74 32.5 0 bottom
Q114  MMBT3904-4-GP  [SOT23CBE2D4H44]  23.11 29.32 270 bottom
Q115  PMBS3906-GP  [SOT-23-10H44]  31.37 157.46 0 top
Q118  2N7002A-7-GP  [SOT23DGS2D4H48]  38.68 152.02 270 top
Q119  2N7002A-7-GP  [SOT23DGS2D4H48]  31.11 151.49 0 top
Q120  2N7002A-7-GP  [SOT23DGS2D4H48]  34.8 151.62 270 top
Q121  2N7002A-7-GP  [SOT23DGS2D4H48]  39.88 157.34 0 top
Q122  2N7002A-7-GP  [SOT23DGS2D4H48]  36.2 157.34 180 top
Q123  2N7002KDW-1-GP  [SOT-363H44]  108.08 86.6 0 top
Q125  AO3401AL-GP  [SOT23DGS2D8H50]  32 60.69 0 top
Q126  MMBT3904-4-GP  [SOT23CBE2D4H44]  18.41 29.57 180 bottom
Q127  MMBT3904-4-GP  [SOT23CBE2D4H44]  21.46 31.68 0 top
Q128  MMBT3904-4-GP  [SOT23CBE2D4H44]  94.01 237.68 270 bottom
Q129  2N7002A-7-GP  [SOT23DGS2D4H48]  131.57 216.21 0 top
QF1  MMBT3904DW-1-GP  [SOT-363H44]  146.18 97.27 90 bottom
R1  100KR2J-1-GP  [R402H16]  96.61 240.75 0 top
R2  10KR2J-3-GP  [R402H16]  91.61 240.67 180 top
R3  0R2J-2-GP  [R402H16]  104.65 236.97 90 top
R4  100KR2J-1-GP  [R402H16]  96.65 237.6 0 top
R5  0R2J-2-GP  [R402H16]  104.65 235.95 90 top
R6  10KR2J-3-GP  [R402H16]  91.65 237.58 0 top
R7  0R2J-2-GP  [R402H16]  104.65 234.93 90 top
R8  0R2J-2-GP  [R402H16]  104.65 233.92 90 top
R9  0R2J-2-GP  [R402H16]  104.65 232.9 90 top
R10  8K2R2J-3-GP  [R402H16]  91 233.89 90 top
R11  0R2J-2-GP  [R402H16]  96.87 233.72 0 top
R12  0R2J-2-GP  [R402H16]  104.65 231.89 90 top
R13  39K2R2F-L-GP  [R402H16]  90.99 232.81 270 top
R14  0R2J-2-GP  [R402H16]  104.65 230.87 90 top
R15  0R2J-2-GP  [R402H16]  96.91 231.55 180 top
R16  0R2J-2-GP  [R402H16]  104.65 229.85 90 top
R17  0R0402-PAD-2-GP  [0R0402-PAD-1]  105.16 228.71 90 top
R18  10KR2J-3-GP  [R402H16]  96.93 229.55 180 top
R19  0R0402-PAD-2-GP  [0R0402-PAD-1]  105.92 226.68 90 top
R20  0R0402-PAD-2-GP  [0R0402-PAD-1]  105.92 227.69 270 top
R21  0R5J-5-GP  [R805H24]  94.23 226.63 90 top
R22  0R0402-PAD-2-GP  [0R0402-PAD-1]  107.19 223.5 0 top
R23  0R0402-PAD-2-GP  [0R0402-PAD-1]  108.2 223.5 0 top
R24  0R0402-PAD-2-GP  [0R0402-PAD-1]  110.62 223.5 0 top
R25  0R0402-PAD-2-GP  [0R0402-PAD-1]  113.16 223.5 0 top
R26  0R0402-PAD-2-GP  [0R0402-PAD-1]  114.17 223.5 0 top
R27  0R0402-PAD-2-GP  [0R0402-PAD-1]  111.63 223.5 0 top
R28  1R5J-2-GP  [R805H24]  33.02 223.88 0 top
R29  10KR2J-3-GP  [R402H16]  24.89 224.14 180 top
R30  10KR2J-3-GP  [R402H16]  160.66 223.38 0 top
R31  1KR2J-1-GP  [R402H16]  71.12 223.63 270 top
R32  10KR2J-3-GP  [R402H16]  119.13 211.06 270 top
R33  10KR2J-3-GP  [R402H16]  116.71 222.49 270 top
R34  0R0805-PAD-2-GP-U  [0R0805-PAD-1-U]  23.5 222.11 90 top
R35  10KR2F-2-GP  [R402H16]  62.18 221.01 270 top
R36  100KR2J-1-GP  [R402H16]  118.24 220.84 180 top
R37  10KR2F-2-GP  [R402H16]  64.39 221.09 90 top
R38  10KR2F-2-GP  [R402H16]  62.18 219.87 90 top
R39  NTC-100K-6-GP  [NTC-603H28]  19.81 219.82 0 top
R40  10KR2J-3-GP  [R402H16]  118.24 218.93 0 top
R41  22R2J-2-GP  [R402H16]  119.25 218.93 180 top
R42  10KR2F-2-GP  [R402H16]  62.18 218.72 90 top
R43  1KR2F-3-GP  [R402H16]  126.64 219.01 90 top
R44  10KR2J-3-GP  [R402H16]  132.41 218.68 270 top
R45  10KR2J-3-GP  [R402H16]  151 218.3 180 top
R46  1KR2F-3-GP  [R402H16]  126.64 217.99 90 top
R47  10KR2F-2-GP  [R402H16]  62.18 217.58 90 top
R48  0R0402-PAD-2-GP  [0R0402-PAD-1]  118.75 217.41 90 top
R49  4K7R2J-2-GP  [R402H16]  142.24 216.34 0 top
R50  0R0402-PAD-2-GP  [0R0402-PAD-1]  141.81 214.82 270 top
R51  0R2J-2-GP  [R402H16]  62.76 216.06 0 top
R52  NTC-220K-5-GP  [NTC-402H24]  41.4 215.88 0 top
R53  0R0402-PAD-2-GP  [0R0402-PAD-1]  138.61 212.71 270 top
R54  4K7R2J-2-GP  [R402H16]  141.78 213.78 270 top
R55  150KR2J-GP  [R402H16]  62.74 214.36 90 top
R56  2D2R5J-1-GP  [R805H24]  176.66 214.23 270 top
R57  100KR2J-1-GP  [R402H16]  68.2 213.72 180 top
R58  10KR2J-3-GP  [R402H16]  72.52 208.14 90 top
R59  1K3R2F-1-GP  [R402H16]  63.25 211.95 180 top
R60  4K7R2J-2-GP  [R402H16]  142.75 211.82 0 top
R61  43R2J-GP  [R402H16]  66.12 210.37 180 top
R62  75R2F-2-GP  [R402H16]  63.25 209.91 0 top
R63  665R2F-2-GP  [R402H16]  67.18 210.3 180 top
R64  10KR2J-3-GP  [R402H16]  69.22 210.3 180 top
R65  0R2J-2-GP  [R402H16]  143.31 210.35 90 top
R66  0R2J-2-GP  [R402H16]  146.81 209.79 180 top
R67  0R0402-PAD-2-GP  [0R0402-PAD-1]  128.78 209.53 90 top
R68  4K7R2J-2-GP  [R402H16]  144.78 208.77 180 top
R69  12KR2F-L-GP  [R402H16]  128.78 208.52 90 top
R70  100KR2J-1-GP  [R402H16]  133.99 208.01 180 top
R71  49D9R2F-GP  [R402H16]  64.99 207.12 0 top
R72  0R0402-PAD-2-GP  [0R0402-PAD-1]  66.24 207.1 0 top
R73  150R2F-1-GP  [R402H16]  68.96 206.96 0 top
R74  0R0402-PAD-2-GP  [0R0402-PAD-1]  70.1 206.96 0 top
R75  10KR2J-3-GP  [R402H16]  135.64 206.61 270 top
R76  2D2R5J-1-GP  [R805H24]  176.4 205.6 90 top
R78  10KR2J-3-GP  [R402H16]  133.88 201.79 90 top
R79  1R5J-2-GP  [R805H24]  33.4 201.02 0 top
R81  4K7R2J-2-GP  [R402H16]  131.95 201.79 90 top
R82  10KR2J-3-GP  [R402H16]  135.76 201.43 270 top
R83  10KR2J-3-GP  [R402H16]  129.29 201.41 90 top
R84  10KR2J-3-GP  [R402H16]  25.27 201.15 0 top
R88  0R0805-PAD-2-GP-U  [0R0805-PAD-1-U]  24 198.99 90 top
R90  1KR2J-1-GP  [R402H16]  175.77 196.96 90 top
R91  4K7R2J-2-GP  [R402H16]  130.07 196.35 270 top
R92  10KR2J-3-GP  [R402H16]  131.98 196.35 90 top
R93  10KR2J-3-GP  [R402H16]  133.88 196.35 90 top
R94  4K7R2J-2-GP  [R402H16]  135.79 196.35 270 top
R95  1KR2J-1-GP  [R402H16]  175.77 195.94 270 top
R96  2D2R5J-1-GP  [R805H24]  178.03 195.89 180 top
R97  10KR2J-3-GP  [R402H16]  175.77 193.94 90 top
R98  10KR2F-2-GP  [R402H16]  179.2 190.74 0 top
R99  45K3R2F-L-GP  [R402H16]  178.82 188.58 180 top
R100  11K5R2F-GP  [R402H16]  180.97 188.58 0 top
R101  10KR2F-2-GP  [R402H16]  183.01 188.58 0 top
R102  470KR2F-GP  [R402H16]  184.02 188.58 0 top
R103  0R0402-PAD-2-GP  [0R0402-PAD-1]  176.23 188.45 0 top
R104  1KR2J-1-GP  [R402H16]  179.83 186.55 180 top
R105  10KR2J-3-GP  [R402H16]  184.15 186.17 270 top
R106  10KR2J-3-GP  [R402H16]  184.15 185.02 270 top
R107  10KR2F-2-GP  [R402H16]  179.83 184.51 180 top
R108  2D2R5J-1-GP  [R805H24]  22.61 170.42 90 top
R109  0R5J-5-GP  [R805H24]  14.15 158.28 180 top
R110  0R5J-5-GP  [R805H24]  16.18 158.28 180 top
R111  1R5J-2-GP  [R805H24]  33.5 169.25 180 top
R112  51R2J-2-GP  [R402H16]  19.1 166.91 270 top
R113  2D2R5J-1-GP  [R805H24]  22.73 164.32 90 top
R114  0R3J-0-U-GP  [R603H22]  19.05 142.96 270 bottom
R119  10KR3J-L1-GP  [R603H22]  19.05 147.68 90 bottom
R122  0R3J-0-U-GP  [R603H22]  19.05 141.79 270 bottom
R127  0R3J-0-U-GP  [R603H22]  19.05 140.62 270 bottom
R128  33R2J-2-GP  [R402H16]  183.01 155.37 180 top
R129  0R3J-0-U-GP  [R603H22]  19.05 139.46 270 bottom
R138  1KR2F-3-GP  [R402H16]  175.16 150.07 0 top
R139  1KR2F-3-GP  [R402H16]  176.3 150.07 180 top
R141  0R0402-PAD-2-GP  [0R0402-PAD-1]  176.25 148.09 0 top
R145  100R2F-L1-GP-U  [R402H14]  74.88 141.43 0 top
R146  75R2F-2-GP  [R402H16]  72.58 141.42 0 top
R147  100R2F-L1-GP-U  [R402H14]  73.72 141.42 0 top
R150  10KR2J-3-GP  [R402H16]  18.08 153.58 0 top
R151  33R2J-2-GP  [R402H16]  15.98 151.67 0 top
R152  1K5R2J-3-GP  [R402H16]  28.42 151.09 180 top
R153  0R0402-PAD-2-GP  [0R0402-PAD-1]  141.99 136.31 180 top
R154  0R0402-PAD-2-GP  [0R0402-PAD-1]  143 136.31 180 top
R155  100KR2J-1-GP  [R402H16]  20.7 148.19 90 top
R156  15KR2F-GP  [R402H16]  23.72 148.45 90 top
R157  0R2J-2-GP  [R402H16]  15.52 149.31 270 top
R158  0R0402-PAD-2-GP  [0R0402-PAD-1]  17.5 148.19 270 top
R159  0R2J-2-GP  [R402H16]  15.52 148.27 270 top
R160  10KR2J-3-GP  [R402H16]  15.47 144.89 90 top
R161  10KR2J-3-GP  [R402H16]  16.99 145.35 0 top
R162  6K04R2F-GP  [R402H16]  91.11 125 180 top
R163  2K67R2F-2-GP  [R402H16]  92.25 125 0 top
R164  1KR2J-1-GP  [R402H16]  14.22 123.05 270 top
R165  10KR2J-3-GP  [R402H16]  16.1 122.28 0 top
R166  10KR2J-3-GP  [R402H16]  14.22 121.9 270 top
R167  100KR2J-1-GP  [R402H16]  14.22 120.63 270 top
R168  0R2J-2-GP  [R402H16]  17.02 120.63 90 top
R169  4K7R2J-2-GP  [R402H16]  14.22 119.36 270 top
R170  0R0402-PAD-2-GP  [0R0402-PAD-1]  17.02 119.36 270 top
R171  10KR2J-3-GP  [R402H16]  16.26 117.97 270 top
R172  10KR2J-3-GP  [R402H16]  16.26 116.95 270 top
R173  4K7R2J-2-GP  [R402H16]  17.4 114.16 180 top
R174  4K7R2J-2-GP  [R402H16]  14.1 112.12 270 top
R175  100KR2J-1-GP  [R402H16]  16.13 112.12 90 top
R176  10KR2J-3-GP  [R402H16]  14.1 110.98 90 top
R177  0R0402-PAD-2-GP  [0R0402-PAD-1]  16.13 110.98 270 top
R178  0R0402-PAD-2-GP  [0R0402-PAD-1]  138.3 114.03 0 top
R179  0R0402-PAD-2-GP  [0R0402-PAD-1]  139.32 114.03 0 top
R180  1KR2J-1-GP  [R402H16]  140.46 114.03 180 top
R181  0R0402-PAD-2-GP  [0R0402-PAD-1]  141.6 114.03 0 top
R182  0R0402-PAD-2-GP  [0R0402-PAD-1]  142.75 114.03 0 top
R183  0R0402-PAD-2-GP  [0R0402-PAD-1]  143.89 114.03 0 top
R184  1KR2J-1-GP  [R402H16]  145.03 114.03 180 top
R185  1KR2J-1-GP  [R402H16]  14.1 109.84 90 top
R186  10KR2J-3-GP  [R402H16]  16.13 109.84 270 top
R187  2D2R5J-1-GP  [R805H24]  171.96 108.7 90 top
R188  1KR2J-1-GP  [R402H16]  14.1 108.44 90 top
R189  10KR2J-3-GP  [R402H16]  16.13 108.44 270 top
R190  -  [0R0805-PAD]  178.82 107.93 180 top
R191  -  [0R0805-PAD]  180.97 107.93 180 top
R192  -  [0R0805-PAD]  147.32 106.41 90 top
R193  0R5J-5-GP  [R805H24]  14.12 105.88 0 top
R194  0R5J-5-GP  [R805H24]  16.15 105.88 0 top
R195  -  [0R0805-PAD]  151.76 105.39 0 top
R196  -  [0R0805-PAD]  153.16 105.39 0 top
R197  -  [0R0805-PAD]  154.56 105.39 0 top
R198  -  [0R0805-PAD]  155.96 105.39 0 top
R199  -  [0R0805-PAD]  157.35 105.39 0 top
R200  2D2R5J-1-GP  [R805H24]  162.81 105.01 90 top
R201  0R5J-5-GP  [R805H24]  147.32 104.38 270 top
R202  2K1R2F-GP  [R402H16]  45.21 101.95 0 top
R203  2K1R2F-GP  [R402H16]  46.35 101.95 180 top
R204  10KR2J-3-GP  [R402H16]  149.81 101.41 0 top
R205  1KR2J-1-GP  [R402H16]  150.88 101.41 180 top
R206  1KR2J-1-GP  [R402H16]  151.92 101.41 180 top
R207  -  [0R0402-PAD]  156.84 101.2 90 top
R208  2D2R5J-1-GP  [R805H24]  170.56 100.95 270 top
R209  40D2R2F-GP  [R402H16]  45.85 100.31 270 top
R210  2D2R5J-1-GP  [R805H24]  167 100.31 180 top
R211  10KR2F-2-GP  [R402H16]  152.91 99.93 90 top
R212  5K11R2F-L1-GP  [R402H16]  155.8 99.7 180 top
R213  10KR2F-2-GP  [R402H16]  157.73 99.7 0 top
R214  470KR2F-GP  [R402H16]  160.02 99.3 90 top
R215  40D2R2F-GP  [R402H16]  45.85 99.2 270 top
R216  20KR2J-L2-GP  [R402H16]  122.68 99.93 0 top
R217  10KR2J-3-GP  [R402H16]  129.67 98.54 90 top
R218  10KR2J-3-GP  [R402H16]  125.7 98.94 270 top
R220  10KR2J-3-GP  [R402H16]  120.4 99.04 0 top
R221  0R2J-2-GP  [R402H16]  179.58 98.41 90 top
R222  0R0402-PAD-2-GP  [0R0402-PAD-1]  181.41 97.89 0 top
R223  10KR2J-3-GP  [R402H16]  138.56 98.03 90 top
R224  10KR2J-3-GP  [R402H16]  141.22 97.65 180 top
R225  10KR2J-3-GP  [R402H16]  142.37 97.65 180 top
R226  1KR2J-1-GP  [R402H16]  143.51 97.65 180 top
R227  0R0402-PAD-2-GP  [0R0402-PAD-1]  184.78 97.39 0 top
R228  47KR2F-GP  [R402H16]  185.93 97.39 0 top
R229  2K1R2F-GP  [R402H16]  44.19 96.24 180 top
R230  2K1R2F-GP  [R402H16]  46.23 96.24 0 top
R231  1KR2J-1-GP  [R402H16]  134.82 96.28 180 top
R232  1KR2J-1-GP  [R402H16]  133.73 96.25 180 top
R233  1KR2J-1-GP  [R402H16]  116.02 95.75 180 top
R234  1KR2J-1-GP  [R402H16]  117.09 95.75 0 top
R235  1KR2J-1-GP  [R402H16]  118.13 95.75 0 top
R236  1KR2J-1-GP  [R402H16]  119.25 97.14 180 top
R237  10KR2J-3-GP  [R402H16]  120.4 97.14 180 top
R238  10KR2J-3-GP  [R402H16]  125.22 95.74 180 top
R239  15R2J-GP  [R402H16]  126.49 96.12 180 top
R240  15R2J-GP  [R402H16]  128.27 95.74 180 top
R241  15R2J-GP  [R402H16]  129.41 95.74 180 top
R242  1KR2J-1-GP  [R402H16]  121.41 95.74 0 top
R243  10KR2J-3-GP  [R402H16]  122.56 95.74 0 top
R244  33R2J-2-GP  [R402H16]  178.85 95.53 0 top
R245  47KR2F-GP  [R402H16]  185.93 95.36 0 top
R246  68R2F-GP  [R402H16]  175.67 94.07 180 top
R247  10KR2J-3-GP  [R402H16]  183.39 94.85 270 top
R249  0R3J-0-U-GP  [R603H22]  170.69 84.57 180 top
R251  1KR2J-1-GP  [R402H16]  144.37 93.89 180 top
R252  1KR2J-1-GP  [R402H16]  141.13 93.91 180 top
R253  0R0402-PAD-2-GP  [0R0402-PAD-1]  142.28 93.91 180 top
R254  51R2J-2-GP  [R402H16]  133.85 93.9 180 top
R255  10KR2J-3-GP  [R402H16]  134.9 93.9 180 top
R256  10KR2J-3-GP  [R402H16]  135.94 93.9 180 top
R257  10KR2J-3-GP  [R402H16]  136.98 93.9 180 top
R258  10KR2J-3-GP  [R402H16]  139.04 93.9 0 top
R259  0R2J-2-GP  [R402H16]  143.32 93.88 0 top
R260  10KR2J-3-GP  [R402H16]  140.08 93.87 0 top
R261  10R2F-L-GP  [R402H14]  187.45 94.34 90 top
R262  10KR2J-3-GP  [R402H16]  188.93 94.07 180 top
R263  0R0402-PAD-2-GP  [0R0402-PAD-1]  172.82 94.98 90 top
R264  10KR2J-3-GP  [R402H16]  120.9 93.46 270 top
R265  2K2R2J-2-GP  [R402H16]  185.8 92.95 90 top
R266  10KR2J-3-GP  [R402H16]  115.95 92.06 180 top
R267  15R2J-GP  [R402H16]  130.68 92.06 180 top
R268  1KR2J-1-GP  [R402H16]  120.53 91.99 0 top
R269  0R2J-2-GP  [R402H16]  118.18 91.97 180 top
R270  10KR2J-3-GP  [R402H16]  119.22 91.97 180 top
R271  10KR2J-3-GP  [R402H16]  121.66 91.97 180 top
R272  10KR2J-3-GP  [R402H16]  122.8 91.97 0 top
R273  1MR2J-1-GP  [R402H16]  148.97 91.96 0 top
R274  1KR2J-1-GP  [R402H16]  123.95 91.93 180 top
R275  0R0402-PAD-2-GP  [0R0402-PAD-1]  150.16 95.61 270 top
R276  10KR2J-3-GP  [R402H16]  138.35 91.33 0 top
R277  10KR2J-3-GP  [R402H16]  139.39 91.33 0 top
R278  10KR2J-3-GP  [R402H16]  136.27 91.3 180 top
R279  10KR2J-3-GP  [R402H16]  150.01 91.25 180 top
R280  10KR2J-3-GP  [R402H16]  143.38 90.44 180 top
R281  390KR2J-GP  [R402H16]  145.67 91.55 0 top
R282  10KR2J-3-GP  [R402H16]  122.04 90.32 270 top
R283  10KR2J-3-GP  [R402H16]  151.82 90.89 270 top
R284  -  [0R0805-PAD]  8.86 89.95 180 top
R287  0R0402-PAD-2-GP  [0R0402-PAD-1]  148.71 89.17 90 top
R289  5D11R3F-1-GP  [R603H22]  151.13 89.05 90 top
R294  4K75R2F-1-GP  [R402H16]  95.5 89.65 90 top
R295  0R5J-5-GP  [R805H24]  13.23 85.94 270 top
R296  4K7R2J-2-GP  [R402H16]  148.21 93.84 270 top
R297  0R2J-2-GP  [R402H16]  153.82 93.99 90 top
R298  390KR2J-GP  [R402H16]  152.14 85.74 270 top
